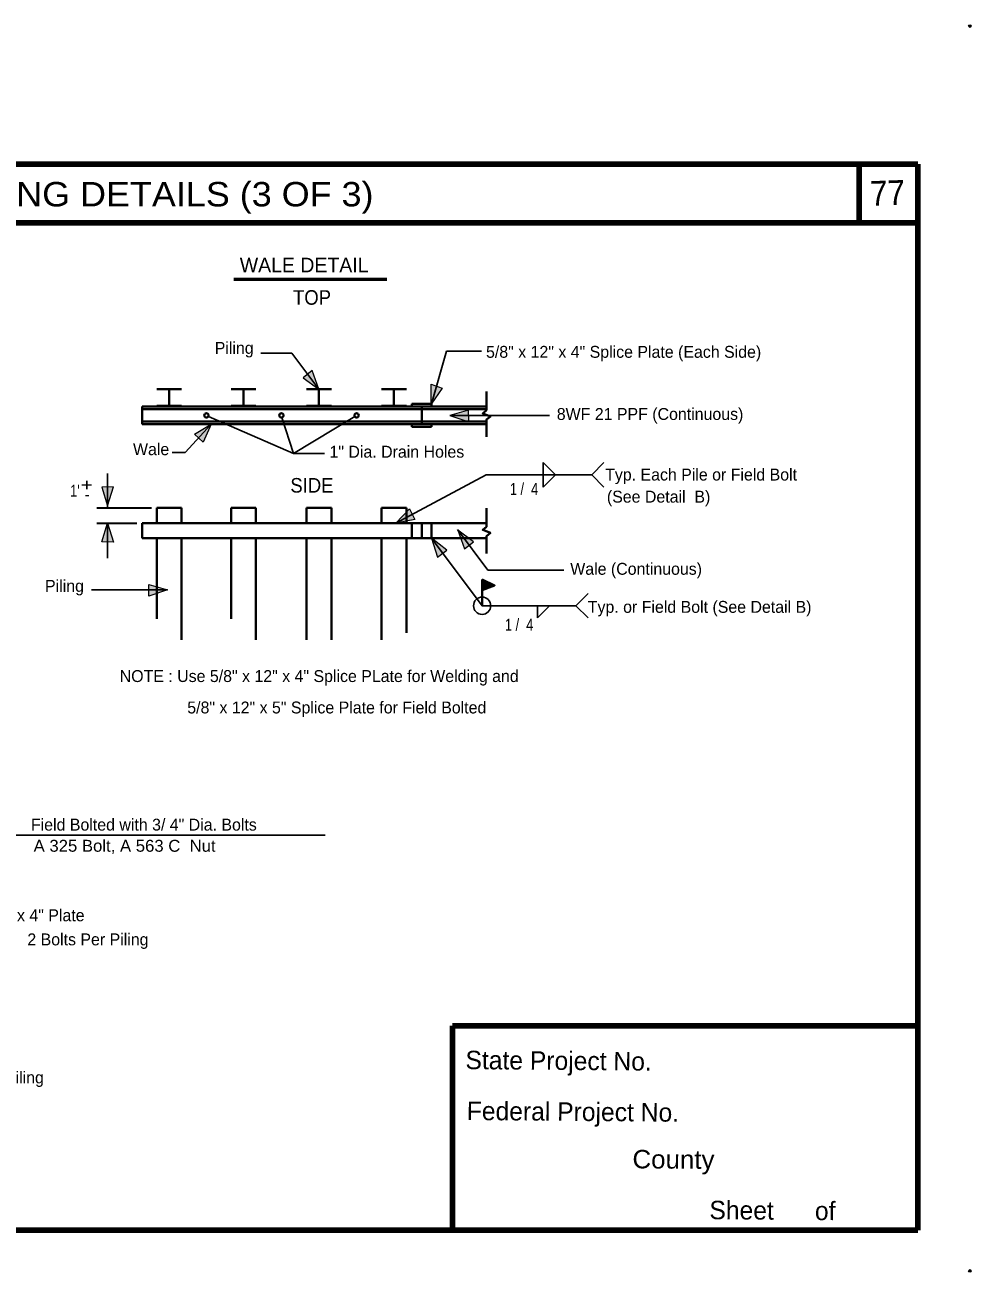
# Model space of a CAD drawing. Extents: x -8731 to -2098, y -70205 to -56618.
# Drawn here: x -3004 to -2098, y -70205 to -69010 of the extents above; entities that cross this region are included whole.
import ezdxf
from ezdxf.enums import TextEntityAlignment as Align

# ---------------------------------------------------------------- set-up
doc = ezdxf.new("R2010")
doc.units = 0
doc.header["$LTSCALE"] = 4.6
doc.header["$PDMODE"] = 32
doc.header["$PDSIZE"] = 2.3
doc.layers.add('1', color=7, linetype='Continuous', lineweight=13)
doc.layers.add('3', color=7, linetype='Continuous', lineweight=40)

msp = doc.modelspace()

# ---------------------------------------------------------------- hatches: boundary and pattern name
at = {"layer": '1'}
for points in [[(-2722.52, -69359.36), (-2728.94, -69341.44), (-2737.72, -69348.48)], [(-2614.9, -69373.82), (-2615.14, -69354.78), (-2604.46, -69358.32)], [(-2597.12, -69384.72), (-2579.04, -69390.68), (-2579.18, -69379.44)], [(-2825.72, -69392.96), (-2833.46, -69410.36), (-2841.68, -69402.68)], [(-2925.32, -69471.2), (-2919.34, -69453.12), (-2930.6, -69453.26)], [(-2648.86, -69487.92), (-2635.64, -69474.22), (-2630.54, -69484.24)], [(-2925.32, -69487.92), (-2919.34, -69506), (-2930.6, -69505.84)], [(-2589.46, -69494.52), (-2583.22, -69512.52), (-2574.38, -69505.56)], [(-2614.66, -69502.32), (-2609.02, -69520.5), (-2599.94, -69513.84)], [(-2867.56, -69551.82), (-2885.64, -69557.78), (-2885.5, -69546.52)]]:
    msp.add_hatch(color=256, dxfattribs=at).paths.add_polyline_path(points)

# ---------------------------------------------------------------- linework, layer by layer
at = {"layer": '1', "lineweight": 100}
for p, q in [((-2148.78, -69143.8), (-3641.02, -69143.8)), ((-2205.02, -69143.8), (-2205.02, -69200.06)), ((-2148.78, -69143.8), (-2148.78, -70165.24)), ((-2148.78, -69200.06), (-3641.02, -69200.06)), ((-2594.5, -69969.56), (-2148.78, -69969.56)), ((-2594.5, -69969.56), (-2594.5, -70165.24)), ((-2148.78, -70165.24), (-2788.92, -70165.24))]:
    msp.add_line(p, q, dxfattribs=at)
msp.add_lwpolyline([(-3641.02, -69147.3), (-3641.02, -70165.24), (-2150.26, -70165.24)], dxfattribs=at)
at = {"layer": '1'}
for points in [[(-2722.52, -69359.36), (-2728.94, -69341.44), (-2737.72, -69348.48)], [(-2614.9, -69373.82), (-2615.14, -69354.78), (-2604.46, -69358.32)], [(-2597.12, -69384.72), (-2579.04, -69390.68), (-2579.18, -69379.44)], [(-2825.72, -69392.96), (-2833.46, -69410.36), (-2841.68, -69402.68)], [(-2925.32, -69471.2), (-2919.34, -69453.12), (-2930.6, -69453.26)], [(-2648.86, -69487.92), (-2635.64, -69474.22), (-2630.54, -69484.24)], [(-2925.32, -69487.92), (-2919.34, -69506), (-2930.6, -69505.84)], [(-2589.46, -69494.52), (-2583.22, -69512.52), (-2574.38, -69505.56)], [(-2614.66, -69502.32), (-2609.02, -69520.5), (-2599.94, -69513.84)], [(-2867.56, -69551.82), (-2885.64, -69557.78), (-2885.5, -69546.52)]]:
    msp.add_lwpolyline(points, close=True, dxfattribs=at)
for p in [(-2098.86, -69011.6), (-2098.86, -70204.2)]:
    msp.add_point(p, dxfattribs=at)
at = {"layer": '3', "lineweight": 53}
msp.add_line((-2803.96, -69254.06), (-2657.56, -69254.06), dxfattribs=at)
at = {"layer": '3', "lineweight": 25}
for p, q in [((-2778.16, -69324.86), (-2748.46, -69324.86)), ((-2748.46, -69324.86), (-2722.52, -69359.36)), ((-2600.26, -69322.92), (-2614.66, -69373.46)), ((-2600.26, -69322.92), (-2566.96, -69322.92)), ((-2828.42, -69385.46), (-2746.82, -69421.02)), ((-2758.06, -69386.52), (-2746.82, -69421.02)), ((-2597.12, -69384.72), (-2501.56, -69384.72)), ((-2825.72, -69392.96), (-2850.62, -69420.12)), ((-2863.36, -69420.12), (-2850.62, -69420.12)), ((-2507.56, -69441.42), (-2507.56, -69429.72)), ((-2507.56, -69429.72), (-2495.86, -69441.42)), ((-2461.22, -69441.42), (-2449.52, -69429.72)), ((-2925.32, -69440.36), (-2925.32, -69473.06)), ((-2562.32, -69441.42), (-2648.86, -69487.92)), ((-2562.32, -69441.42), (-2461.22, -69441.42)), ((-2507.56, -69453.26), (-2507.56, -69441.42)), ((-2507.56, -69453.26), (-2495.86, -69441.42)), ((-2461.22, -69441.42), (-2449.52, -69453.26)), ((-2925.32, -69487.92), (-2925.32, -69521.22)), ((-2589.92, -69493.92), (-2560.82, -69532.92)), ((-2560.82, -69532.92), (-2487.92, -69532.92)), ((-2940.46, -69551.82), (-2867.56, -69551.82)), ((-2476.36, -69566.96), (-2464.66, -69555.12)), ((-2513.26, -69578.66), (-2513.26, -69566.96)), ((-2513.26, -69578.66), (-2501.56, -69566.96)), ((-2476.36, -69566.96), (-2464.66, -69578.66)), ((-3019.82, -69786.86), (-2716.52, -69786.86))]:
    msp.add_line(p, q, dxfattribs=at)
at = {"layer": '3'}
for p, q in [((-2877.92, -69359.36), (-2854.22, -69359.36)), ((-2866.06, -69359.36), (-2866.06, -69375.26)), ((-2806.82, -69359.36), (-2783.12, -69359.36)), ((-2794.96, -69359.36), (-2794.96, -69375.26)), ((-2734.36, -69359.36), (-2710.66, -69359.36)), ((-2722.52, -69359.36), (-2722.52, -69375.26)), ((-2662.66, -69359.36), (-2638.82, -69359.36)), ((-2650.66, -69359.36), (-2650.66, -69375.26)), ((-2877.92, -69375.26), (-2854.22, -69375.26)), ((-2806.82, -69375.26), (-2783.12, -69375.26)), ((-2734.36, -69375.26), (-2710.66, -69375.26)), ((-2662.66, -69375.26), (-2638.82, -69375.26)), ((-2633.42, -69373.46), (-2614.66, -69373.46)), ((-2633.42, -69373.46), (-2633.42, -69376.16)), ((-2614.66, -69373.46), (-2614.66, -69376.16)), ((-2892.02, -69376.16), (-2562.02, -69376.16)), ((-2892.02, -69376.16), (-2892.02, -69392.96)), ((-2892.02, -69378.72), (-2562.02, -69378.72)), ((-2623.96, -69376.16), (-2623.96, -69392.96)), ((-2892.02, -69390.26), (-2562.02, -69390.26)), ((-2892.02, -69392.96), (-2562.02, -69392.96)), ((-2633.42, -69392.96), (-2633.42, -69395.66)), ((-2633.42, -69395.66), (-2614.66, -69395.66)), ((-2614.66, -69392.96), (-2614.66, -69395.66)), ((-2877.92, -69473.06), (-2854.22, -69473.06)), ((-2877.92, -69487.92), (-2877.92, -69473.06)), ((-2854.22, -69487.92), (-2854.22, -69473.06)), ((-2806.82, -69487.92), (-2806.82, -69473.06)), ((-2806.82, -69473.06), (-2783.12, -69473.06)), ((-2783.12, -69487.92), (-2783.12, -69473.06)), ((-2734.36, -69487.92), (-2734.36, -69473.06)), ((-2734.36, -69473.06), (-2710.66, -69473.06)), ((-2710.66, -69487.92), (-2710.66, -69473.06)), ((-2662.66, -69487.92), (-2662.66, -69473.06)), ((-2662.66, -69473.06), (-2638.82, -69473.06)), ((-2638.82, -69487.92), (-2638.82, -69473.06)), ((-2892.02, -69487.92), (-2562.02, -69487.92)), ((-2892.02, -69502.32), (-2892.02, -69487.92)), ((-2633.42, -69502.32), (-2633.42, -69487.92)), ((-2623.96, -69502.32), (-2623.96, -69487.92)), ((-2614.66, -69502.32), (-2614.66, -69487.92)), ((-2892.02, -69502.32), (-2562.02, -69502.32)), ((-2877.92, -69579.42), (-2877.92, -69502.32)), ((-2854.22, -69599.66), (-2854.22, -69502.32)), ((-2806.82, -69579.42), (-2806.82, -69502.32)), ((-2783.12, -69599.66), (-2783.12, -69502.32)), ((-2734.36, -69599.66), (-2734.36, -69502.32)), ((-2710.66, -69599.66), (-2710.66, -69502.32)), ((-2662.66, -69599.66), (-2662.66, -69502.32)), ((-2638.82, -69592.76), (-2638.82, -69502.32)), ((-2566.22, -69566.96), (-2566.22, -69541.92)), ((-2554.22, -69547.46), (-2566.22, -69541.92)), ((-2554.82, -69547.76), (-2566.22, -69542.36)), ((-2555.56, -69547.92), (-2566.22, -69542.96)), ((-2556.02, -69548.06), (-2566.22, -69543.42)), ((-2556.62, -69548.36), (-2566.22, -69543.86)), ((-2557.22, -69548.66), (-2566.22, -69544.46)), ((-2557.82, -69548.82), (-2566.22, -69545.06)), ((-2558.26, -69549.12), (-2566.22, -69545.36)), ((-2558.86, -69549.26), (-2566.22, -69545.96)), ((-2559.46, -69549.56), (-2566.22, -69546.42)), ((-2560.22, -69549.86), (-2566.22, -69547.02)), ((-2560.82, -69550.02), (-2566.22, -69547.46)), ((-2561.26, -69550.16), (-2566.22, -69547.92)), ((-2561.86, -69550.46), (-2566.22, -69548.36)), ((-2562.62, -69550.76), (-2566.22, -69549.12)), ((-2563.22, -69550.92), (-2566.22, -69549.56)), ((-2563.52, -69551.06), (-2566.22, -69549.86)), ((-2564.12, -69551.36), (-2566.22, -69550.32)), ((-2564.56, -69551.52), (-2566.22, -69550.62)), ((-2565.16, -69551.66), (-2566.22, -69551.22)), ((-2565.92, -69551.96), (-2566.22, -69551.66))]:
    msp.add_line(p, q, dxfattribs=at)
at = {"layer": '3', "lineweight": 35}
for p, q in [((-2935.52, -69473.06), (-2883.02, -69473.06)), ((-2935.52, -69487.92), (-2897.12, -69487.92))]:
    msp.add_line(p, q, dxfattribs=at)
at = {"layer": '3'}
for points in [[(-2562.02, -69361.62), (-2562.02, -69379.46), (-2565.62, -69382.62), (-2558.26, -69385.62), (-2562.02, -69388.62), (-2562.02, -69405.12)], [(-2562.02, -69473.36), (-2562.02, -69491.22), (-2565.62, -69494.36), (-2558.26, -69497.22), (-2562.02, -69500.36), (-2562.02, -69516.86)], [(-2566.22, -69552.12), (-2554.22, -69547.46), (-2566.22, -69541.92)]]:
    msp.add_lwpolyline(points, dxfattribs=at)
at = {"layer": '3', "lineweight": 25}
for points in [[(-2688.16, -69385.62), (-2746.82, -69421.02), (-2717.12, -69421.02)], [(-2614.66, -69502.32), (-2566.22, -69566.96), (-2476.36, -69566.96)]]:
    msp.add_lwpolyline(points, dxfattribs=at)
at = {"layer": '3'}
for centre in [(-2830.36, -69384.52), (-2758.58, -69384.52), (-2686.48, -69384.52)]:
    msp.add_circle(centre, 2.09, dxfattribs=at)
at = {"layer": '3', "lineweight": 25}
msp.add_circle((-2566.19, -69566.96), 8.28, dxfattribs=at)

# ---------------------------------------------------------------- texts
at = {"layer": '1'}
for s, height, rotation, width, p in [('77', 23.78, 2.121, 0.95, (-2194.06, -69183.94)), ('County', 17.66, 359.537, 1.05, (-2422.22, -70105.92))]:
    msp.add_text(s, height=height, rotation=rotation, dxfattribs=dict(at, width=width)).set_placement(p)
for s, p in [('State Project No.', (-2582.22, -70010.92)), ('Federal Project No.', (-2580.98, -70059.68)), ('Sheet      of', (-2348.48, -70154.68))]:
    msp.add_text(s, height=17.66, rotation=359.537, dxfattribs=at).set_placement(p)
at = {"layer": '3', "width": 1.1}
msp.add_text('  PILING DETAILS (3 OF 3) ', height=23.4, dxfattribs=at).set_placement((-2876.86, -69184.32), align=Align.CENTER)
at = {"layer": '3'}
for s, height, p in [('WALE DETAIL', 13.95, (-2798.42, -69247.46)), ('Piling', 11.4, (-2822.42, -69325.62)), ('5/8" x 12" x 4" Splice Plate (Each Side)', 11.4, (-2562.46, -69329.36)), ('8WF 21 PPF (Continuous)', 11.4, (-2494.66, -69388.92)), ('Wale', 11.4, (-2900.72, -69422.66)), ('1" Dia. Drain Holes', 11.4, (-2712.46, -69425.06)), ('Typ. Each Pile or Field Bolt ', 11.4, (-2448.32, -69446.96)), ('(See Detail  B)', 11.4, (-2446.66, -69468.12)), ('-', 11.4, (-2947.22, -69465.96)), ('Wale (Continuous)', 11.4, (-2481.76, -69537.26)), ('Piling', 11.4, (-2985.02, -69553.62)), ('Typ. or Field Bolt (See Detail B)', 11.4, (-2464.96, -69573.72)), ('NOTE : Use 5/8" x 12" x 4" Splice PLate for Welding and', 11.4, (-2913.46, -69640.02)), ('5/8" x 12" x 5" Splice Plate for Field Bolted', 11.4, (-2848.72, -69670.12)), ('Field Bolted with 3/ 4" Dia. Bolts', 11.4, (-2998.52, -69782.36)), ('Splice 5/8" x 12" x 4" Plate', 11.4, (-3126.92, -69869.22)), ('2 Bolts Per Piling', 11.4, (-3001.96, -69892.32)), ('Piling', 11.4, (-3023.42, -70024.62))]:
    msp.add_text(s, height=height, dxfattribs=at).set_placement(p)
for s, height, width, p in [('TOP', 13.95, 0.95, (-2747.42, -69278.52)), ('+', 11.4, 1.3, (-2950.82, -69456.72)), ('SIDE', 13.95, 0.95, (-2749.96, -69458.52)), ("1'", 11.4, 0.8, (-2960.96, -69462.46)), ('1 /  4', 11.4, 0.8, (-2539.62, -69460.72)), ('1 /  4', 11.4, 0.8, (-2544.32, -69590.82)), ('A 325 Bolt, A 563 C  Nut', 11.4, 1.05, (-2995.96, -69802.62))]:
    msp.add_text(s, height=height, dxfattribs=dict(at, width=width)).set_placement(p)

doc.saveas('drawing.dxf')
